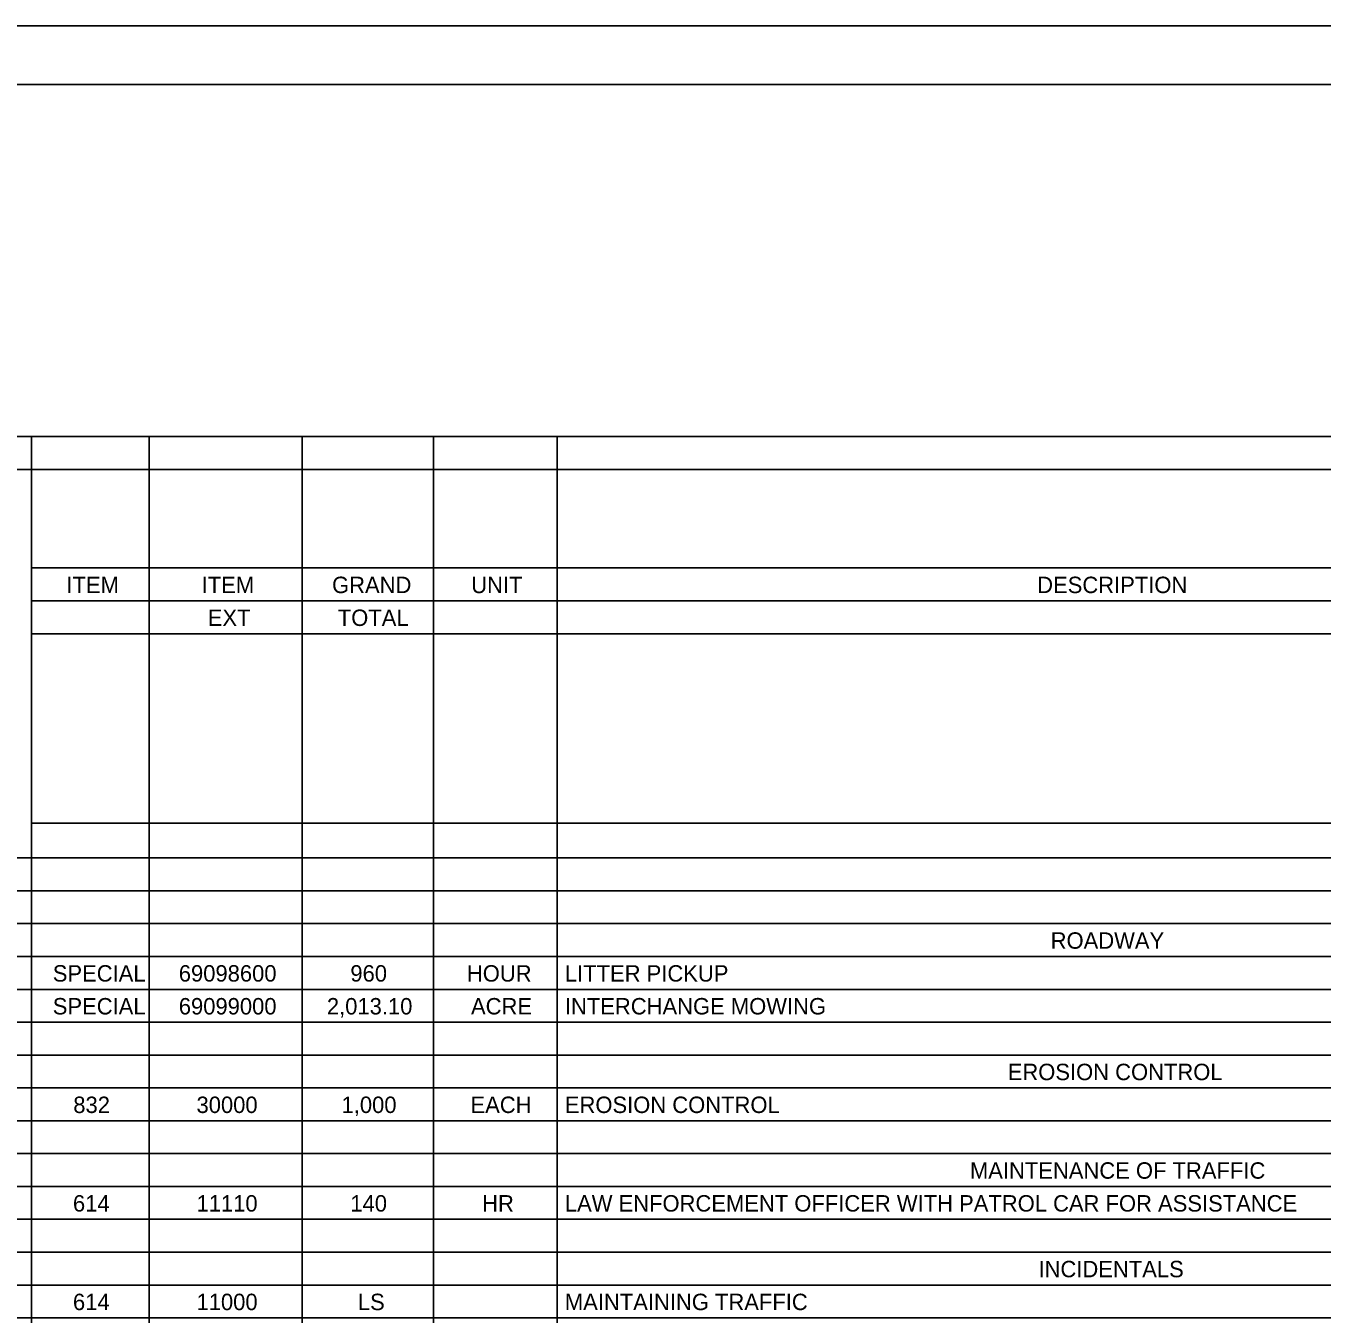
# Model space of a CAD drawing. Extents: x 0 to 34, y 0 to 22.
# Drawn here: x 11.97 to 23.01, y 11.02 to 22 of the extents above; entities that cross this region are included whole.
import ezdxf

# ---------------------------------------------------------------- set-up
doc = ezdxf.new("R2010")
doc.units = 0
for name, color, linetype in [('SH_Border', 7, 'Continuous'), ('SH_Cut_Line', 7, 'Continuous'), ('SH_Data', 7, 'Continuous'), ('SH_Text', 7, 'Continuous')]:
    doc.layers.add(name, color=color, linetype=linetype)

msp = doc.modelspace()

# ---------------------------------------------------------------- linework, layer by layer
at = {"layer": 'SH_Border'}
msp.add_lwpolyline([(1.5, 21.5), (33.5, 21.5), (33.5, 0.5), (1.5, 0.5)], close=True, dxfattribs=at)
at = {"layer": 'SH_Cut_Line'}
msp.add_lwpolyline([(0, 0), (34, 0), (34, 22), (0, 22)], close=True, dxfattribs=at)
at = {"layer": 'SH_Data'}
for p, q in [((6, 18.5), (27.049, 18.5)), ((12.012, 18.5), (12.012, 14.909)), ((13.016, 18.5), (13.016, 14.909)), ((14.318, 18.5), (14.318, 14.909)), ((15.438, 18.5), (15.438, 14.909)), ((16.492, 18.5), (16.492, 2.853)), ((10.216, 18.22), (12.012, 18.22)), ((6, 14.909), (27.049, 14.909)), ((12.012, 14.909), (12.012, 2.853)), ((13.016, 14.909), (13.016, 2.853)), ((14.318, 14.909), (14.318, 2.853)), ((15.438, 14.909), (15.438, 2.853)), ((6, 14.629), (27.049, 14.629)), ((6, 14.349), (27.049, 14.349)), ((6, 14.069), (27.049, 14.069)), ((6, 13.789), (27.049, 13.789)), ((6, 13.509), (27.049, 13.509)), ((6, 13.229), (27.049, 13.229)), ((6, 12.949), (27.049, 12.949)), ((6, 12.669), (27.049, 12.669)), ((6, 12.389), (27.049, 12.389)), ((6, 12.109), (27.049, 12.109)), ((6, 11.829), (27.049, 11.829)), ((6, 11.549), (27.049, 11.549)), ((6, 11.269), (27.049, 11.269))]:
    msp.add_line(p, q, dxfattribs=at)
at = {"layer": 'SH_Text'}
for points in [[(10.216, 18.5), (12.012, 18.5), (12.012, 18.22), (10.216, 18.22)], [(12.012, 18.5), (13.016, 18.5), (13.016, 18.22), (12.012, 18.22)], [(13.016, 18.5), (14.318, 18.5), (14.318, 18.22), (13.016, 18.22)], [(14.318, 18.5), (15.438, 18.5), (15.438, 18.22), (14.318, 18.22)], [(15.438, 18.5), (16.492, 18.5), (16.492, 18.22), (15.438, 18.22)], [(16.492, 18.5), (25.765, 18.5), (25.765, 18.22), (16.492, 18.22)], [(10.216, 18.22), (12.012, 18.22), (12.012, 14.909), (10.216, 14.909)], [(12.012, 18.22), (13.016, 18.22), (13.016, 17.38), (12.012, 17.38)], [(13.016, 18.22), (14.318, 18.22), (14.318, 17.38), (13.016, 17.38)], [(14.318, 18.22), (15.438, 18.22), (15.438, 17.38), (14.318, 17.38)], [(15.438, 18.22), (16.492, 18.22), (16.492, 17.38), (15.438, 17.38)], [(16.492, 18.22), (25.765, 18.22), (25.765, 17.38), (16.492, 17.38)], [(12.012, 17.38), (13.016, 17.38), (13.016, 17.1), (12.012, 17.1)], [(13.016, 17.38), (14.318, 17.38), (14.318, 17.1), (13.016, 17.1)], [(14.318, 17.38), (15.438, 17.38), (15.438, 17.1), (14.318, 17.1)], [(15.438, 17.38), (16.492, 17.38), (16.492, 17.1), (15.438, 17.1)], [(16.492, 17.38), (25.765, 17.38), (25.765, 17.1), (16.492, 17.1)], [(12.012, 17.1), (13.016, 17.1), (13.016, 16.82), (12.012, 16.82)], [(13.016, 17.1), (14.318, 17.1), (14.318, 16.82), (13.016, 16.82)], [(14.318, 17.1), (15.438, 17.1), (15.438, 16.82), (14.318, 16.82)], [(15.438, 17.1), (16.492, 17.1), (16.492, 16.82), (15.438, 16.82)], [(16.492, 17.1), (25.765, 17.1), (25.765, 16.82), (16.492, 16.82)], [(12.012, 16.82), (13.016, 16.82), (13.016, 15.206), (12.012, 15.206)], [(13.016, 16.82), (14.318, 16.82), (14.318, 15.206), (13.016, 15.206)], [(14.318, 16.82), (15.438, 16.82), (15.438, 15.206), (14.318, 15.206)], [(15.438, 16.82), (16.492, 16.82), (16.492, 15.206), (15.438, 15.206)], [(16.492, 16.82), (25.765, 16.82), (25.765, 15.206), (16.492, 15.206)], [(10.216, 14.909), (12.012, 14.909), (12.012, 14.629), (10.216, 14.629)], [(12.012, 14.909), (13.016, 14.909), (13.016, 14.629), (12.012, 14.629)], [(13.016, 14.909), (14.318, 14.909), (14.318, 14.629), (13.016, 14.629)], [(14.318, 14.909), (15.438, 14.909), (15.438, 14.629), (14.318, 14.629)], [(15.438, 14.909), (16.492, 14.909), (16.492, 14.629), (15.438, 14.629)], [(16.492, 14.909), (25.765, 14.909), (25.765, 14.629), (16.492, 14.629)], [(10.216, 14.629), (12.012, 14.629), (12.012, 14.349), (10.216, 14.349)], [(12.012, 14.629), (13.016, 14.629), (13.016, 14.349), (12.012, 14.349)], [(13.016, 14.629), (14.318, 14.629), (14.318, 14.349), (13.016, 14.349)], [(14.318, 14.629), (15.438, 14.629), (15.438, 14.349), (14.318, 14.349)], [(15.438, 14.629), (16.492, 14.629), (16.492, 14.349), (15.438, 14.349)], [(16.492, 14.629), (25.765, 14.629), (25.765, 14.349), (16.492, 14.349)], [(10.216, 14.349), (12.012, 14.349), (12.012, 14.069), (10.216, 14.069)], [(12.012, 14.349), (13.016, 14.349), (13.016, 14.069), (12.012, 14.069)], [(13.016, 14.349), (14.318, 14.349), (14.318, 14.069), (13.016, 14.069)], [(14.318, 14.349), (15.438, 14.349), (15.438, 14.069), (14.318, 14.069)], [(15.438, 14.349), (16.492, 14.349), (16.492, 14.069), (15.438, 14.069)], [(16.492, 14.349), (25.765, 14.349), (25.765, 14.069), (16.492, 14.069)], [(10.216, 14.069), (12.012, 14.069), (12.012, 13.789), (10.216, 13.789)], [(12.012, 14.069), (13.016, 14.069), (13.016, 13.789), (12.012, 13.789)], [(13.016, 14.069), (14.318, 14.069), (14.318, 13.789), (13.016, 13.789)], [(14.318, 14.069), (15.438, 14.069), (15.438, 13.789), (14.318, 13.789)], [(15.438, 14.069), (16.492, 14.069), (16.492, 13.789), (15.438, 13.789)], [(16.492, 14.069), (25.765, 14.069), (25.765, 13.789), (16.492, 13.789)], [(10.216, 13.789), (12.012, 13.789), (12.012, 13.509), (10.216, 13.509)], [(12.012, 13.789), (13.016, 13.789), (13.016, 13.509), (12.012, 13.509)], [(13.016, 13.789), (14.318, 13.789), (14.318, 13.509), (13.016, 13.509)], [(14.318, 13.789), (15.438, 13.789), (15.438, 13.509), (14.318, 13.509)], [(15.438, 13.789), (16.492, 13.789), (16.492, 13.509), (15.438, 13.509)], [(16.492, 13.789), (25.765, 13.789), (25.765, 13.509), (16.492, 13.509)], [(10.216, 13.509), (12.012, 13.509), (12.012, 13.229), (10.216, 13.229)], [(12.012, 13.509), (13.016, 13.509), (13.016, 13.229), (12.012, 13.229)], [(13.016, 13.509), (14.318, 13.509), (14.318, 13.229), (13.016, 13.229)], [(14.318, 13.509), (15.438, 13.509), (15.438, 13.229), (14.318, 13.229)], [(15.438, 13.509), (16.492, 13.509), (16.492, 13.229), (15.438, 13.229)], [(16.492, 13.509), (25.765, 13.509), (25.765, 13.229), (16.492, 13.229)], [(10.216, 13.229), (12.012, 13.229), (12.012, 12.949), (10.216, 12.949)], [(12.012, 13.229), (13.016, 13.229), (13.016, 12.949), (12.012, 12.949)], [(13.016, 13.229), (14.318, 13.229), (14.318, 12.949), (13.016, 12.949)], [(14.318, 13.229), (15.438, 13.229), (15.438, 12.949), (14.318, 12.949)], [(15.438, 13.229), (16.492, 13.229), (16.492, 12.949), (15.438, 12.949)], [(16.492, 13.229), (25.765, 13.229), (25.765, 12.949), (16.492, 12.949)], [(10.216, 12.949), (12.012, 12.949), (12.012, 12.669), (10.216, 12.669)], [(12.012, 12.949), (13.016, 12.949), (13.016, 12.669), (12.012, 12.669)], [(13.016, 12.949), (14.318, 12.949), (14.318, 12.669), (13.016, 12.669)], [(14.318, 12.949), (15.438, 12.949), (15.438, 12.669), (14.318, 12.669)], [(15.438, 12.949), (16.492, 12.949), (16.492, 12.669), (15.438, 12.669)], [(16.492, 12.949), (25.765, 12.949), (25.765, 12.669), (16.492, 12.669)], [(10.216, 12.669), (12.012, 12.669), (12.012, 12.389), (10.216, 12.389)], [(12.012, 12.669), (13.016, 12.669), (13.016, 12.389), (12.012, 12.389)], [(13.016, 12.669), (14.318, 12.669), (14.318, 12.389), (13.016, 12.389)], [(14.318, 12.669), (15.438, 12.669), (15.438, 12.389), (14.318, 12.389)], [(15.438, 12.669), (16.492, 12.669), (16.492, 12.389), (15.438, 12.389)], [(16.492, 12.669), (25.765, 12.669), (25.765, 12.389), (16.492, 12.389)], [(10.216, 12.389), (12.012, 12.389), (12.012, 12.109), (10.216, 12.109)], [(12.012, 12.389), (13.016, 12.389), (13.016, 12.109), (12.012, 12.109)], [(13.016, 12.389), (14.318, 12.389), (14.318, 12.109), (13.016, 12.109)], [(14.318, 12.389), (15.438, 12.389), (15.438, 12.109), (14.318, 12.109)], [(15.438, 12.389), (16.492, 12.389), (16.492, 12.109), (15.438, 12.109)], [(16.492, 12.389), (25.765, 12.389), (25.765, 12.109), (16.492, 12.109)], [(10.216, 12.109), (12.012, 12.109), (12.012, 11.829), (10.216, 11.829)], [(12.012, 12.109), (13.016, 12.109), (13.016, 11.829), (12.012, 11.829)], [(13.016, 12.109), (14.318, 12.109), (14.318, 11.829), (13.016, 11.829)], [(14.318, 12.109), (15.438, 12.109), (15.438, 11.829), (14.318, 11.829)], [(15.438, 12.109), (16.492, 12.109), (16.492, 11.829), (15.438, 11.829)], [(16.492, 12.109), (25.765, 12.109), (25.765, 11.829), (16.492, 11.829)], [(10.216, 11.829), (12.012, 11.829), (12.012, 11.549), (10.216, 11.549)], [(12.012, 11.829), (13.016, 11.829), (13.016, 11.549), (12.012, 11.549)], [(13.016, 11.829), (14.318, 11.829), (14.318, 11.549), (13.016, 11.549)], [(14.318, 11.829), (15.438, 11.829), (15.438, 11.549), (14.318, 11.549)], [(15.438, 11.829), (16.492, 11.829), (16.492, 11.549), (15.438, 11.549)], [(16.492, 11.829), (25.765, 11.829), (25.765, 11.549), (16.492, 11.549)], [(10.216, 11.549), (12.012, 11.549), (12.012, 11.269), (10.216, 11.269)], [(12.012, 11.549), (13.016, 11.549), (13.016, 11.269), (12.012, 11.269)], [(13.016, 11.549), (14.318, 11.549), (14.318, 11.269), (13.016, 11.269)], [(14.318, 11.549), (15.438, 11.549), (15.438, 11.269), (14.318, 11.269)], [(15.438, 11.549), (16.492, 11.549), (16.492, 11.269), (15.438, 11.269)], [(16.492, 11.549), (25.765, 11.549), (25.765, 11.269), (16.492, 11.269)], [(10.216, 11.269), (12.012, 11.269), (12.012, 10.989), (10.216, 10.989)], [(12.012, 11.269), (13.016, 11.269), (13.016, 10.989), (12.012, 10.989)], [(13.016, 11.269), (14.318, 11.269), (14.318, 10.989), (13.016, 10.989)], [(14.318, 11.269), (15.438, 11.269), (15.438, 10.989), (14.318, 10.989)], [(15.438, 11.269), (16.492, 11.269), (16.492, 10.989), (15.438, 10.989)], [(16.492, 11.269), (25.765, 11.269), (25.765, 10.989), (16.492, 10.989)]]:
    msp.add_lwpolyline(points, close=True, dxfattribs=at)

# ---------------------------------------------------------------- texts
for s, p in [('ITEM', (12.31, 17.166)), ('ITEM', (13.463, 17.166)), ('GRAND', (14.574, 17.166)), ('UNIT', (15.76, 17.166)), ('DESCRIPTION', (20.583, 17.166)), ('EXT', (13.515, 16.886)), ('TOTAL', (14.623, 16.886)), ('ROADWAY', (20.698, 14.135)), ('SPECIAL', (12.194, 13.855)), ('69098600', (13.268, 13.855)), ('960', (14.73, 13.855)), ('HOUR', (15.723, 13.855)), ('LITTER PICKUP', (16.558, 13.855)), ('SPECIAL', (12.194, 13.575)), ('69099000', (13.268, 13.575)), ('2,013.10', (14.53, 13.575)), ('ACRE', (15.758, 13.575)), ('INTERCHANGE MOWING', (16.558, 13.575)), ('EROSION CONTROL', (20.332, 13.015)), ('832', (12.369, 12.735)), ('30000', (13.419, 12.735)), ('1,000', (14.655, 12.735)), ('EACH', (15.754, 12.735)), ('EROSION CONTROL', (16.558, 12.735)), ('MAINTENANCE OF TRAFFIC', (20.01, 12.175)), ('614', (12.366, 11.895)), ('11110', (13.419, 11.895)), ('140', (14.73, 11.895)), ('HR', (15.853, 11.895)), ('LAW ENFORCEMENT OFFICER WITH PATROL CAR FOR ASSISTANCE', (16.558, 11.895)), ('INCIDENTALS', (20.594, 11.335)), ('614', (12.366, 11.055)), ('11000', (13.419, 11.055)), ('LS', (14.794, 11.055)), ('MAINTAINING TRAFFIC', (16.558, 11.055))]:
    msp.add_text(s, height=0.14, dxfattribs=at).set_placement(p)

doc.saveas('drawing.dxf')
